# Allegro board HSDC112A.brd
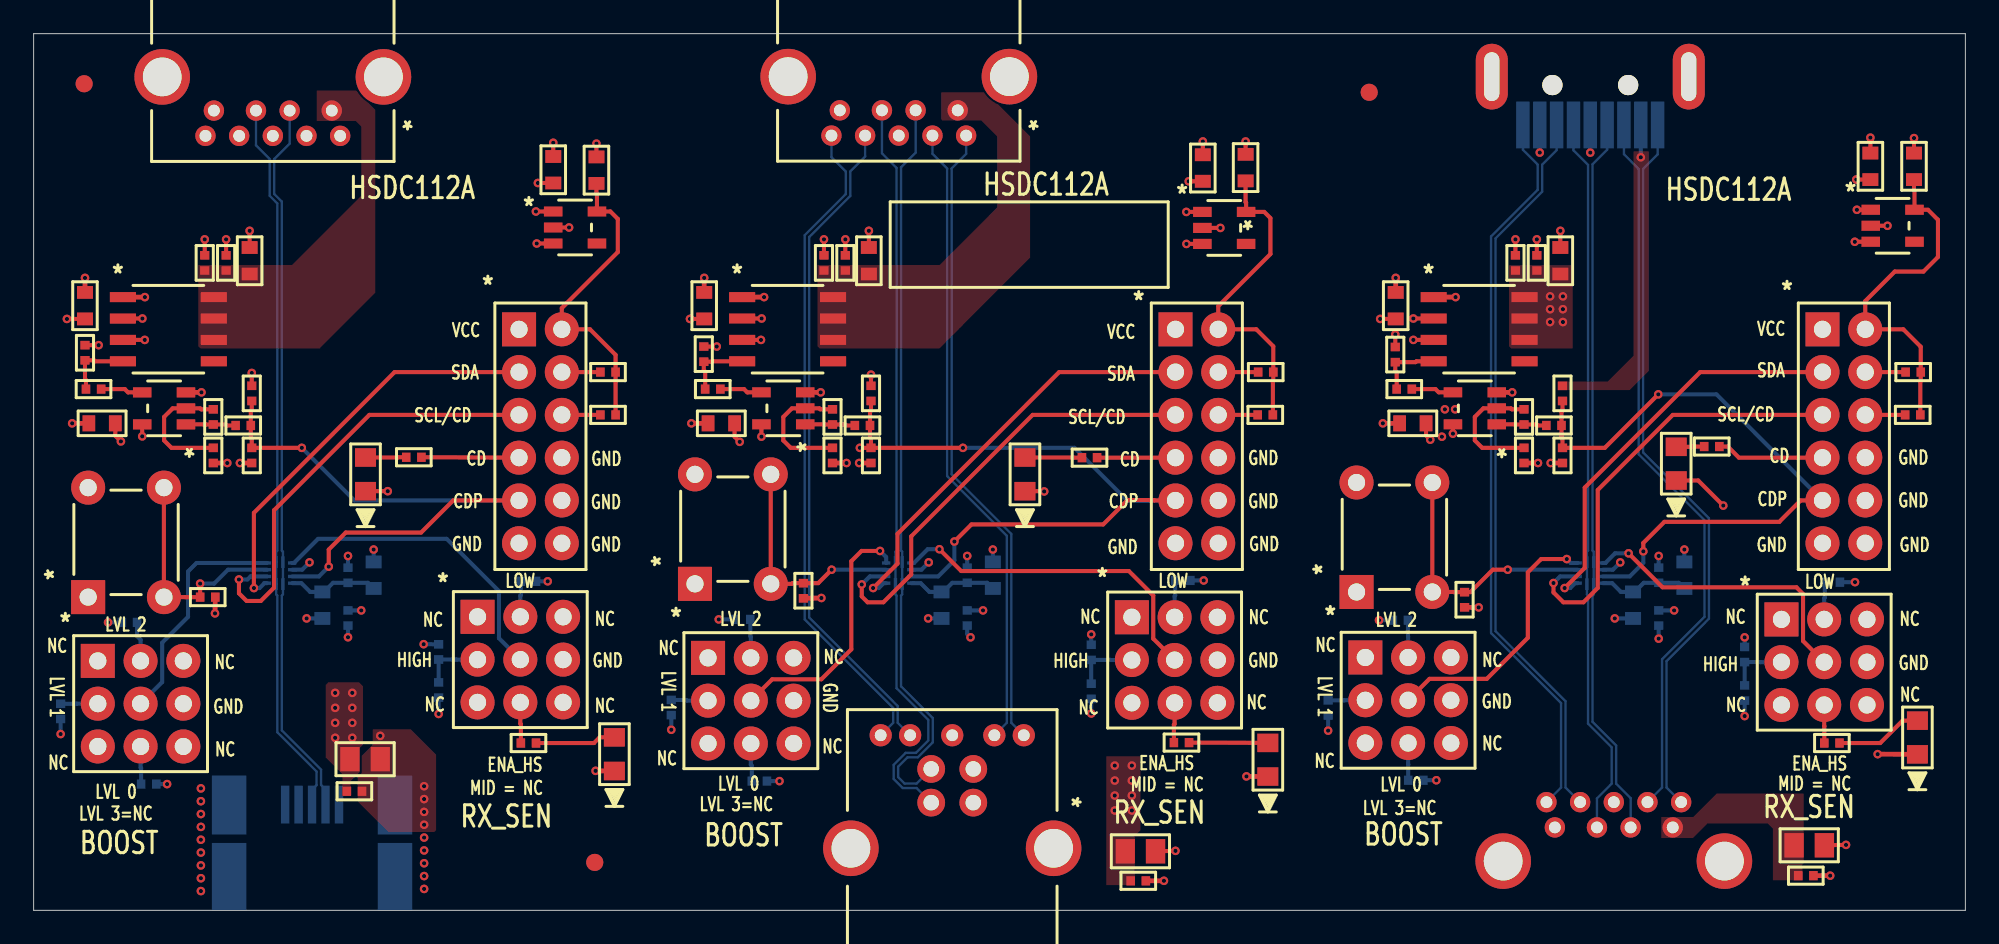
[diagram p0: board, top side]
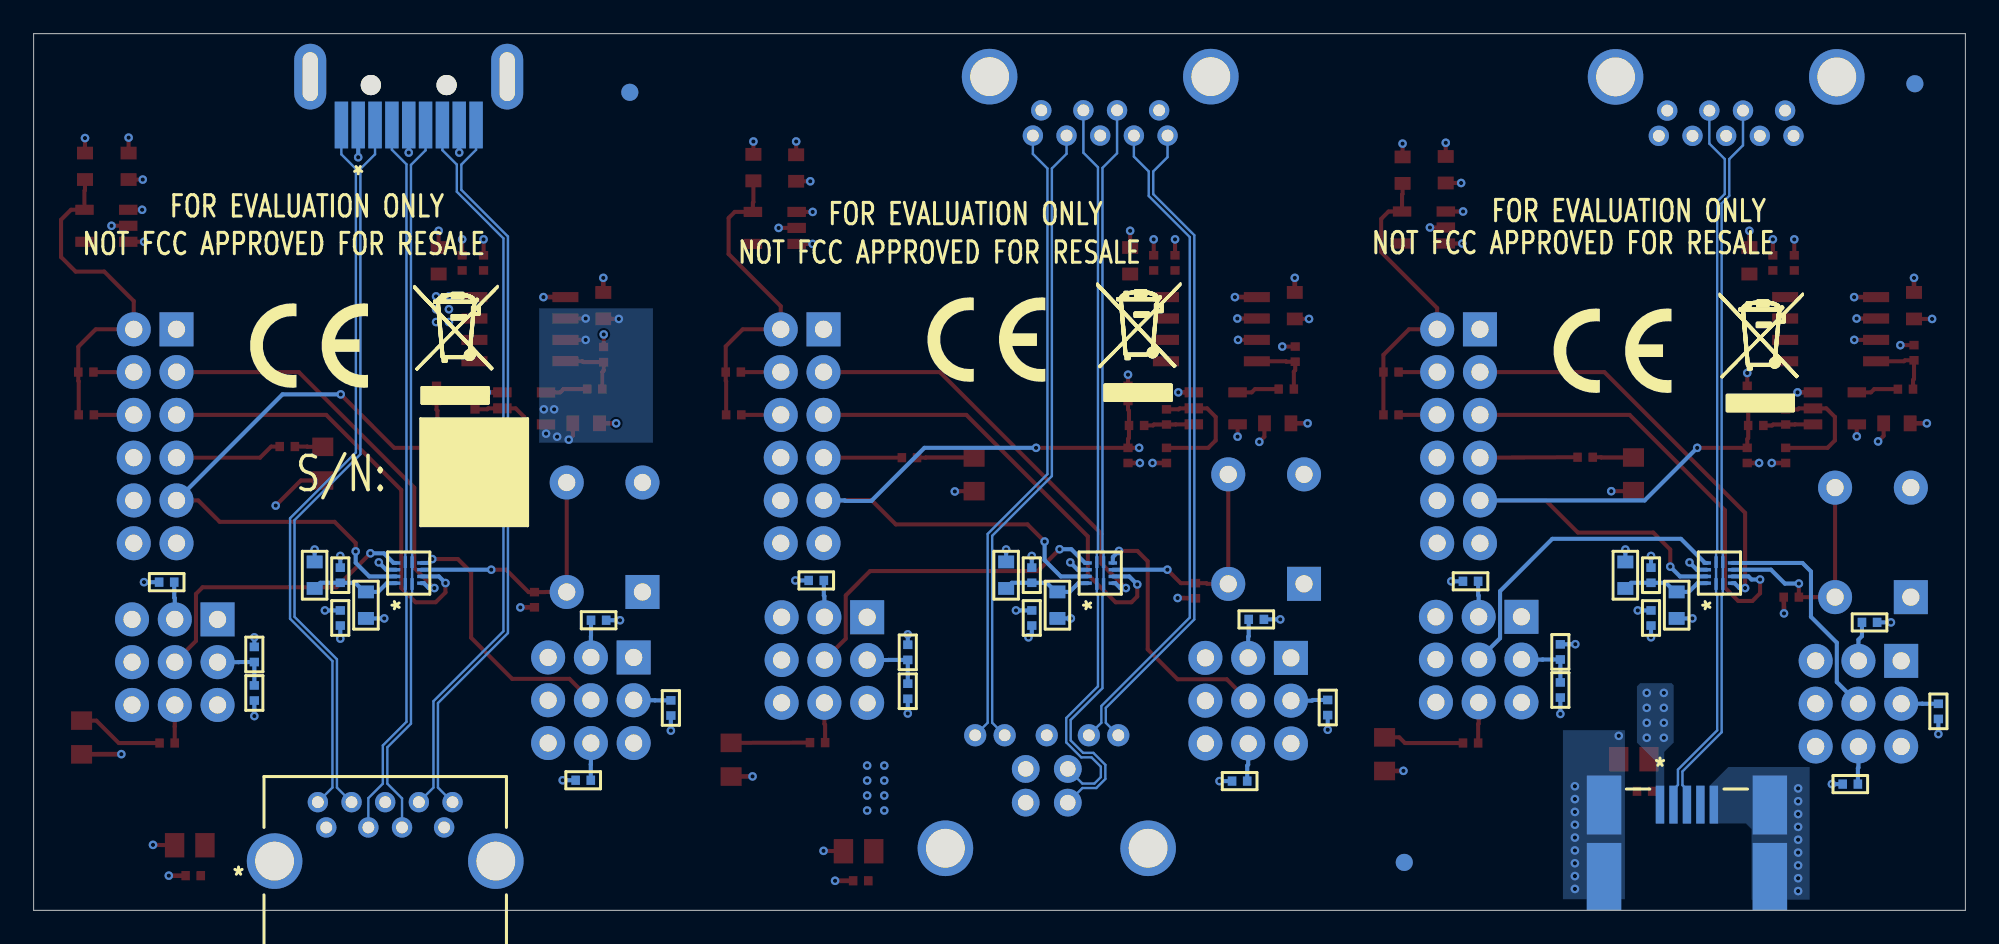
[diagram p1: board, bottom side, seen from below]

Outline 114.73 x 52.04 mm; copper layers: TOP, L2_PWR, L3_GND, BOTTOM. Coordinates in mm from the lower left corner of the outline.
Outline path: 0,52.04 114.73,52.04 114.73,0 0,0 0,52.04

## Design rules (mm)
constraint set DEFAULT: min track width 0.241
net group DIFFPAIR1: nets D1M_P1 D1P_P1
net group DIFFPAIR2: nets SS_RXN_P2 SS_RXP_P2
net group DIFFPAIR4: nets SS_TXN_P2 SS_TXP_P2
net group DIFFPAIR5: nets D1M_P2 D1P_P2
net group DIFFPAIR6: nets SS_TXN_P3 SS_TXP_P3
net group DIFFPAIR8: nets SS_RXN_P3 SS_RXP_P3
net group DIFFPAIR9: nets D1M_P3 D1P_P3

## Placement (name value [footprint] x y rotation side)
C1  0.1uF  [CAP_0402]  19.05 7.07 0 top
C2  10uF  [CAP_0805]  19.68 8.97 0 top
C3  1uF  [CAP_0603]  20.19 19.89 90 bottom
C4  0.1uF  [CAP_0402]  18.67 19.89 90 bottom
C5  0.1uF  [CAP_0402]  10.34 18.59 0 top
C6  1uF  [CAP_0603]  3.05 35.9 90 top
C7  2.2uF  [CAP_0603]  12.83 38.56 90 top
C8  0.1uF  [CAP_0402]  10.16 38.44 90 top
C9  0.1uF  [CAP_0402]  11.43 38.44 90 top
C10  1uF  [CAP_0603]  4.06 28.91 180 top
C11  4.7uF  [CAP_0402]  10.67 27.01 270 top
C12  0.1uF  [CAP_0402]  65.61 1.75 0 top
C13  10uF  [CAP_0805]  65.74 3.51 0 top
C14  1uF  [CAP_0603]  56.97 19.9 90 bottom
C15  0.1uF  [CAP_0402]  55.45 19.9 90 bottom
C16  0.1uF  [CAP_0402]  45.72 18.97 270 top
C17  2.2uF  [CAP_0603]  49.61 38.56 90 top
C18  0.1uF  [CAP_0402]  46.94 38.44 90 top
C19  0.1uF  [CAP_0402]  48.21 38.44 90 top
C20  1uF  [CAP_0603]  39.83 35.9 90 top
C21  1uF  [CAP_0603]  40.84 28.91 180 top
C22  4.7uF  [CAP_0402]  47.45 27.01 270 top
C23  0.1uF  [CAP_0402]  105.26 2.06 0 top
C24  10uF  [CAP_0805]  105.46 3.86 0 top
C25  1uF  [CAP_0603]  98.04 19.9 90 bottom
C26  0.1uF  [CAP_0402]  96.52 19.9 90 bottom
C27  0.1uF  [CAP_0402]  84.99 18.44 270 top
C28  2.2uF  [CAP_0603]  90.68 38.56 90 top
C29  0.1uF  [CAP_0402]  88.01 38.44 90 top
C30  0.1uF  [CAP_0402]  89.28 38.44 90 top
C31  1uF  [CAP_0603]  80.9 35.9 90 top
C32  1uF  [CAP_0603]  81.92 28.91 180 top
C33  4.7uF  [CAP_0402]  88.52 27.01 270 top
C34  1uF  [CAP_0603]  30.86 43.97 90 top
C35  2.2uF  [CAP_0603]  33.43 43.94 90 top
C36  1uF  [CAP_0603]  69.44 44.07 90 top
C37  2.2uF  [CAP_0603]  71.98 44.09 90 top
C38  1uF  [CAP_0603]  109.09 44.17 90 top
C39  2.2uF  [CAP_0603]  111.68 44.17 90 top
D1  LED  [LED_SM_LTST-C171]  19.71 25.88 90 top
D2  LED  [LED_SM_LTST-C171]  34.49 9.27 90 top
D3  LED  [LED_SM_LTST-C171]  73.3 8.94 90 top
D4  LED  [LED_SM_LTST-C171]  58.88 25.88 90 top
D5  LED  [LED_SM_LTST-C171]  111.89 10.26 90 top
D6  LED  [LED_SM_LTST-C171]  97.56 26.52 90 top
J1  HEADER 3x3  [HDR_THVT_3X3_254_871]  28.91 14.88 0 top
J2  HEADER 3x3  [HDR_THVT_3X3_254_871]  6.35 12.27 0 top
J3  HEADER 3x3  [HDR_THVT_3X3_254_871]  67.77 14.86 0 top
J4  HEADER 3x3  [HDR_THVT_3X3_254_871]  42.6 12.45 0 top
J5  HEADER 3x3  [HDR_THVT_3X3_254_871]  106.35 14.73 0 top
J6  HEADER 3x3  [HDR_THVT_3X3_254_871]  81.64 12.47 0 top
JMP1  Header 6x2  [HDR_THVT_2X6_254_871]  28.83 34.49 0 top
JMP8  Header 6x2  [HDR_THVT_2X6_254_871]  106.25 34.49 0 top
JMP9  Header 6x2  [HDR_THVT_2X6_254_871]  67.82 34.49 0 top
L1  100ohms  [FB_0603]  17.14 18.12 90 bottom
L2  100ohms  [FB_0603]  53.92 18.12 90 bottom
L3  100ohms  [FB_0603]  95 18.12 90 bottom
NOREF  -  []  23.24 43.26 0 top
NOREF#2  -  []  -3.81 -69.85 0 top
NOREF#3  -  []  0 52.04 0 top
NOREF#4  -  []  0 0 0 top
NOREF#5  -  []  114.73 0 90 top
NOREF#6  -  [unnamed#2]  33.32 2.84 0 top
NOREF#7  -  []  88.9 38.1 0 top
NOREF#8  -  []  60.6 43.38 0 top
NOREF#9  -  [unnamed#2]  3 49.07 0 top
NOREF#10  -  []  100.13 43.26 0 top
NOREF#11  -  [unnamed#2]  79.32 48.56 0 top
NOREF#12  -  [unnamed#2]  79.32 48.56 180 bottom
NOREF#13  -  []  20.95 33.22 180 bottom
NOREF#14  -  []  58.14 33.88 180 bottom
NOREF#15  -  []  98.73 26.01 180 bottom
NOREF#16  -  [unnamed#2]  33.32 2.84 180 bottom
NOREF#17  -  []  49.07 34.26 180 bottom
NOREF#18  -  []  98.37 33.53 180 bottom
NOREF#19  -  []  89.64 34.11 180 bottom
NOREF#20  -  []  12.12 33.66 180 bottom
NOREF#21  -  [unnamed#2]  3 49.07 180 bottom
P1  USB3.0 Type A Receptacle  [USB-A_THRT_GSB311131HR]  14.2 49.48 180 top
P2  Mini USB B  [USB-MB_SMRT_0548191572]  16.54 2 180 bottom
P3  USB3.0 Type A Receptacle  [USB-A_THRT_GSB311131HR]  51.38 49.49 180 top
P4  USB3.0 Type B Receptacle  [USB-B_THRT_GSB3211311WEU]  54.56 3.68 270 top
P5  USB3.0 Type A Receptacle  [USB-A_THRT_GSB311131HR]  93.85 2.92 180 bottom
P6  USB 3.0 Type A  [USB-A_SMRT_GSB316441CEU]  92.46 49.49 0 bottom
R1  0  [RES_0402]  18.67 17.35 90 bottom
R2  27 k  [RES_0402]  29.39 19.53 180 bottom
R3  1 k  [RES_0402]  3.05 33.1 270 top
R4  75  [RES_0402]  22.58 26.9 180 top
R5  75  [RES_0402]  29.39 9.93 0 top
R6  3.6 k  [RES_0402]  5.69 17.09 180 bottom
R7  0  [RES_0402]  6.83 7.49 0 bottom
R8  1.8 k  [RES_0402]  1.6 11.81 270 bottom
R9  13 k  [RES_0402]  24.05 15.34 270 bottom
R10  10k 1% DNI  [RES_0402]  12.95 30.69 270 top
R11  39 k  [RES_0402]  24.05 13.08 270 bottom
R12  0 DNI  [RES_0402]  3.56 30.94 0 top
R13  0 DNI  [RES_0402]  12.45 28.78 0 top
R14  22 k  [RES_0402]  10.67 29.29 270 top
R15  75k 1% DNI  [RES_0402]  12.95 27.01 270 top
R16  0  [RES_0402]  55.45 17.36 90 bottom
R17  1 k  [RES_0402]  39.8 33.02 90 top
R18  27 k  [RES_0402]  68.25 19.58 0 bottom
R19  75  [RES_0402]  62.71 26.87 180 top
R20  75  [RES_0402]  68.17 9.96 0 top
R21  3.6 k  [RES_0402]  42.11 17.27 180 bottom
R22  0  [RES_0402]  43.1 7.67 0 bottom
R23  10k 1% DNI  [RES_0402]  49.73 30.69 270 top
R24  1.8 k  [RES_0402]  37.87 12.04 270 bottom
R25  13 k  [RES_0402]  62.81 15.32 270 bottom
R26  0 DNI  [RES_0402]  40.34 30.94 0 top
R27  0 DNI  [RES_0402]  49.23 28.79 0 top
R28  22 k  [RES_0402]  47.45 29.29 270 top
R29  75k 1% DNI  [RES_0402]  49.73 27.01 270 top
R30  39 k  [RES_0402]  62.81 13 270 bottom
R31  0  [RES_0402]  96.52 17.36 90 bottom
R32  27 k  [RES_0402]  106.83 19.48 180 bottom
R33  1 k  [RES_0402]  80.87 32.99 90 top
R34  75  [RES_0402]  106.81 9.93 0 top
R35  75  [RES_0402]  99.67 27.53 180 top
R36  3.6 k  [RES_0402]  81.18 17.22 180 bottom
R37  0  [RES_0402]  82.09 7.72 0 bottom
R38  1.8 k  [RES_0402]  76.89 12.01 270 bottom
R39  13 k  [RES_0402]  101.63 15.19 270 bottom
R40  10k 1% DNI  [RES_0402]  90.81 30.69 270 top
R41  39 k  [RES_0402]  101.63 12.9 270 bottom
R42  0 DNI  [RES_0402]  81.41 30.94 0 top
R43  0 DNI  [RES_0402]  90.3 28.79 0 top
R44  22 k  [RES_0402]  88.52 29.29 270 top
R45  75k 1% DNI  [RES_0402]  90.81 27.01 270 top
R46  4.7 k  [RES_0402]  34.11 31.95 180 top
R47  4.7 k  [RES_0402]  34.11 29.41 180 top
R48  4.7 k  [RES_0402]  73.18 31.95 180 top
R49  4.7 k  [RES_0402]  73.15 29.41 180 top
R50  4.7 k  [RES_0402]  111.63 31.95 180 top
R51  4.7 k  [RES_0402]  111.61 29.41 180 top
SW1  Switch - Push Button  [SW_THVT_PTS645SL50-2]  5.49 21.84 90 top
SW2  Switch - Push Button  [SW_THVT_PTS645SL50-2]  41.53 22.63 90 top
SW3  Switch - Push Button  [SW_THVT_PTS645SL50-2]  80.82 22.15 90 top
U1  TUSB216I_217A_RWB  [RWB0012AA]  14.61 20.02 90 bottom
U2  TPS2024D  [D0008AA]  8 34.5 0 top
U3  SN74AHC1G86DBV  [DBV0005AB]  7.75 29.8 180 top
U4  TUSB216I_217A_RWB  [RWB0012AA]  51.38 20.02 90 bottom
U5  TPS2024D  [D0008AA]  44.78 34.5 0 top
U6  SN74AHC1G86DBV  [DBV0005AB]  44.53 29.8 180 top
U7  TUSB216I_217A_RWB  [RWB0012AA]  92.46 20.02 90 bottom
U8  TPS2024D  [D0008AA]  85.85 34.5 0 top
U9  SN74AHC1G86DBV  [DBV0005AB]  85.6 29.8 180 top
U10  TPS70633  [DBV0005AB]  32.16 40.54 0 top
U11  TPS70633  [DBV0005AB]  70.71 40.51 0 top
U12  TPS70633  [DBV0005AB]  110.41 40.64 0 top

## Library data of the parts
C1 C4 C5 C8 C9 C11 C12 C15 C16 C18 C19 C22 C23 C26 C27 C29 C30 C33 = cc0402
C2 C13 C24 = CAPACITOR POL
C3 C6 C7 C10 C14 C17 C20 C21 C25 C28 C31 C32 C34-C39 = cc0603
D1 D4 D6 = d0805 Blue
D2 D3 D5 = d0805 Green
J1-J6 = HEADER 3x3_0
JMP1 JMP8 JMP9 = Header 6x2
L1-L3 = Ferrite_Bead_500ohm
P1 P3 P5 = USB 3.0 Type A Receptacle
P2 = Mini USB B_3
P4 = USB 3.0 Type B Receptacle
P6 = USB 3_1.0 Type A
R1-R51 = r0402
SW1-SW3 = Switch - Push Button_0
U1 U4 U7 = TUSB216RWB_2
U2 U5 U8 = TPS2024_D_1
U3 U6 U9 = SN74AHC1G86_DBV_
U10-U12 = TPS706

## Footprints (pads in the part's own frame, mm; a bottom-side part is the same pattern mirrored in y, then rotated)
CAP_0402
  rect 0.51x0.55 smd: 1(-0.45,0) 2(0.45,0)
CAP_0603
  rect 0.76x0.95 smd: 1(-0.787,0) 2(0.787,0)
CAP_0805
  rect 1.15x1.45 smd: 1(-0.9,0) 2(0.9,0)
D0008AA
  rect 1.55x0.6 smd: 1(-2.7,1.905) 2(-2.7,0.635) 3(-2.7,-0.635) 4(-2.7,-1.905) 5(2.7,-1.905) 6(2.7,-0.635) 7(2.7,0.635) 8(2.7,1.905)
DBV0005AB
  rect 1.1x0.6 smd: 1(-1.3,0.95) 2(-1.3,0) 3(-1.3,-0.95) 4(1.3,-0.95) 5(1.3,0.95)
FB_0603
  rect 0.76x0.95 smd: 1(-0.787,0) 2(0.787,0)
HDR_THVT_2X6_254_871
  rect 2.02x2.02 hole 1.02: 1(0,0)
  round 2.02 hole 1.02: 2(2.54,0) 3(0,-2.54) 4(2.54,-2.54) 5(0,-5.08) 6(2.54,-5.08) 7(0,-7.62) 8(2.54,-7.62) 9(0,-10.16) 10(2.54,-10.16) 11(0,-12.7) 12(2.54,-12.7)
HDR_THVT_3X3_254_871
  rect 2.02x2.02 hole 1.02: 1(-2.54,2.54)
  round 2.02 hole 1.02: 2(0,2.54) 3(2.54,2.54) 4(-2.54,0) 5(0,0) 6(2.54,0) 7(-2.54,-2.54) 8(0,-2.54) 9(2.54,-2.54)
LED_SM_LTST-C171
  rect 1.1x1.25 smd: 1(-1,0) 2(1,0)
RES_0402
  rect 0.51x0.55 smd: 1(-0.45,0) 2(0.45,0)
RWB0012AA
  rect 0.7x0.2 smd: 1(-0.65,0.2) 2(-0.65,-0.2) 7(0.65,-0.2) 8(0.65,0.2)
  rect 0.2x0.5 smd: 3(-0.6,-0.75) 4(-0.2,-0.75) 5(0.2,-0.75) 6(0.6,-0.75) 9(0.6,0.75) 10(0.2,0.75) 11(-0.2,0.75) 12(-0.6,0.75)
SW_THVT_PTS645SL50-2
  rect 2.02x2.02 hole 1.02: 1(-3.25,2.25)
  round 2.02 hole 1.02: 2(3.25,2.25) 3(-3.25,-2.25) 4(3.25,-2.25)
unnamed#2
  round 1.016 smd: (0,0)
USB-A_SMRT_GSB316441CEU
  round 1.2 hole 1.2 unplated: (-2.25,0.5) (2.25,0.5)
  rect 0.8x2.78 smd: 1(3,2.87) 2(1,2.87) 3(-1,2.87) 4(-3,2.87) 5(-4,2.87) 6(-2,2.87) 7(0,2.87) 8(2,2.87) 9(4,2.87)
  oval 1.9x3.9 hole 0.9x2.9: 10(-5.85,0) 11(5.85,0)
USB-A_THRT_GSB311131HR
  round 1.21 hole 0.7: 1(-3.5,2) 2(-1,2) 3(1,2) 4(3.5,2) 5(4,3.5) 6(2,3.5) 7(0,3.5) 8(-2,3.5) 9(-4,3.5)
  round 3.3 hole 2.3: 10(-6.57,0) 11(6.57,0)
USB-B_THRT_GSB3211311WEU
  round 1.65 hole 0.92: 1(-4.71,1.25) 2(-4.71,-1.25) 3(-2.71,-1.25) 4(-2.71,1.25)
  round 1.32 hole 0.7: 5(-6.71,-4.25) 6(-6.71,-2.5) 7(-6.71,0) 8(-6.71,2.5) 9(-6.71,4.25)
  round 3.3 hole 2.3: 10(0,6.02) 11(0,-6.02)
USB-MB_SMRT_0548191572
  rect 0.5x2.25 smd: 1(-1.6,4.275) 2(-0.8,4.275) 3(0,4.275) 4(0.8,4.275) 5(1.6,4.275)
  rect 2.05x3.5 smd: 6(4.925,4.25) 9(-4.925,4.25)
  rect 2.05x4 smd: 7(4.925,0) 8(-4.925,0)

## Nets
GND: C1.2 C2.2 C3.2 C4.2 C5.2 C6.2 C7.2 C8.2 C9.2 C10.2 C11.2 C12.2 C13.2 C14.2 C15.2 C16.2 C17.2 C18.2 C19.2 C20.2 C21.2 C22.2 C23.2 C24.2 C25.2 C26.2 C27.2 C28.2 C29.2 C30.2 C31.2 C32.2 C33.2 C34.2 C35.2 C36.2 C37.2 C38.2 C39.2 D1.1 D2.1 D3.1 D4.1 D5.1 D6.1 J1.6 J2.6 J3.6 J4.6 J5.6 J6.6 JMP1.8 JMP1.10 JMP1.11 JMP1.12 JMP8.8 JMP8.10 JMP8.11 JMP8.12 JMP9.8 JMP9.10 JMP9.11 JMP9.12 P1.4 P1.7 P1.10 P1.11 P2.5 P2.6 P2.7 P2.8 P2.9 P3.4 P3.7 P3.10 P3.11 P4.4 P4.7 P4.10 P4.11 P5.4 P5.7 P5.10 P5.11 P6.4 P6.7 P6.10 P6.11 R2.1 R3.1 R6.2 R7.2 R8.2 R11.2 R15.2 R17.2 R18.2 R21.2 R22.2 R24.2 R29.2 R30.2 R32.1 R33.2 R36.2 R37.2 R38.2 R41.2 R45.2 SW1.1 SW1.2 SW2.1 SW2.2 SW3.1 SW3.2 U1.10 U2.1 U3.3 U4.10 U5.1 U6.3 U7.10 U8.1 U9.3 U10.2 U11.2 U12.2
VBUS_DS_P1: C7.1 C8.1 C9.1 P1.1(VBUS) U2.6 U2.7 U2.8(OUT_2)
VBUS_DS_P2: C17.1 C18.1 C19.1 P3.1(VBUS) U5.6 U5.7 U5.8(OUT_2)
VBUS_DS_P3: C23.1 C24.1 C28.1 C29.1 C30.1 P5.1(VBUS) U8.6 U8.7 U8.8(OUT_2)
VBUS_US_P3: P6.1(VBUS) R31.1 R40.1
VCC_EXT_P1: C6.1 C10.1 C34.1 JMP1.1 L1.1 R1.2 R9.1 U2.2 U2.3 U3.5 U10.1 U10.3
VCC_EXT_P2: C20.1 C21.1 C36.1 JMP9.1 L2.1 R16.2 R25.1 U5.2 U5.3 U6.5 U11.1 U11.3
VCC_EXT_P3: C31.1 C32.1 C38.1 JMP8.1 L3.1 R31.2 R39.1 U8.2 U8.3 U9.5 U12.1 U12.3
VCC_US_P1: C1.1 C2.1 P2.1(VBUS) R1.1 R10.1
VCC_US_P2: C12.1 C13.1 P4.1(VBUS) R16.1 R23.1
BOOST_P1: J2.5 U1.6
BOOST_P2: J4.5 U4.6
BOOST_P3: J6.5 U7.6
CD_P1: JMP1.7 R4.1
CD_P2: JMP9.7 R19.1
CD_P3: JMP8.7 R35.1
CDP_ENZ_P1: JMP1.9 R10.2 R13.2 R15.1 U1.11
CDP_ENZ_P2: JMP9.9 R23.2 R27.2 R29.1 U4.11
CDP_ENZ_P3: JMP8.9 R40.2 R43.2 R45.1 U7.11
D1M_P1: P1.2 P2.2 U1.1 U1.8
D1M_P2: P3.2 P4.2 U4.1 U4.8
D1M_P3: P5.2 P6.2 U7.1 U7.8
D1P_P1: P1.3 P2.3 U1.2 U1.7
D1P_P2: P3.3 P4.3 U4.2 U4.7
D1P_P3: P5.3 P6.3 U7.2 U7.7
DCP_CDP_TOGGLE_P1: R3.2 R12.1 U2.4
DCP_CDP_TOGGLE_P2: R17.1 R26.1 U5.4
DCP_CDP_TOGGLE_P3: R33.1 R42.1 U8.4
ENA_HS_P1: J1.8 R5.1
ENA_HS_P2: J3.8 R20.1
ENA_HS_P3: J5.8 R34.1
RSTN_P1: C5.1 SW1.3 SW1.4 U1.5
RSTN_P2: C16.1 SW2.3 SW2.4 U4.5
RSTN_P3: C27.1 SW3.3 SW3.4 U7.5
RX_SEN/ENA_HS_P1: J1.5 U1.9
RX_SEN/ENA_HS_P2: J3.5 U4.9
RX_SEN/ENA_HS_P3: J5.5 U7.9
SCL/CD_P1: JMP1.5 U1.4
SCL/CD_P2: JMP9.5 U4.4
SCL/CD_P3: JMP8.5 U7.4
SDA_P1: JMP1.3 U1.3
SDA_P2: JMP9.3 U4.3
SDA_P3: JMP8.3 U7.3
SS_RXN_P2: P3.5 P4.5
SS_RXN_P3: P5.5 P6.5
SS_RXP_P2: P3.6 P4.6
SS_RXP_P3: P5.6 P6.6
SS_TXN_P2: P3.8 P4.8
SS_TXN_P3: P5.8 P6.8
SS_TXP_P2: P3.9 P4.9
SS_TXP_P3: P5.9 P6.9
SW_VCC_P1: C35.1 JMP1.2 R46.1 R47.1 U10.5(VOUT)
SW_VCC_P2: C37.1 JMP9.2 R48.1 R49.1 U11.5(VOUT)
SW_VCC_P3: C39.1 JMP8.2 R50.1 R51.1 U12.5(VOUT)
N16790170: R27.1 R28.2 U6.1
N16790175: C22.1 R28.1 U6.2
N16793543: R26.2 U6.4(Y)
N16795852: R43.1 R44.2 U9.1
N16795856: C33.1 R44.1 U9.2
N16796357: R42.2 U9.4(Y)
N16796414: D6.2 R35.2
N16797569: R13.1 R14.2 U3.1
N16798025: C3.1 C4.1 L1.2 U1.12(VCC)
N16798074: R12.2 U3.4(Y)
N16798131: D1.2 R4.2
N16810380: J1.4 R9.2 R11.1
N16810407: J2.8 R7.1
N16810514: J2.2 R6.1
N16813878: C14.1 C15.1 L2.2 U4.12(VCC)
N16814597: C25.1 C26.1 L3.2 U7.12(VCC)
N16860679: J3.4 R25.2 R30.1
N16860703: J4.8 R22.1
N16860789: J4.2 R21.1
N16861643: J5.4 R39.2 R41.1
N16861663: J6.4 R38.1
N16861667: J6.8 R37.1
N16861753: J6.2 R36.1
N16876268: C11.1 R14.1 U3.2
N16883773: D4.2 R19.2
N16915178: JMP1.4 R46.2
N16915181: JMP1.6 R47.2
N16916526: JMP9.6 R49.2
N16916965: JMP9.4 R48.2
N16917043: JMP8.6 R51.2
N16917272: JMP8.4 R50.2
N16929690: J1.2 R2.2
N16931613: J2.4 R8.1
N16933252: J3.2 R18.1
N16935144: J4.4 R24.1
N16936334: J5.2 R32.2
N168104220: D2.2 R5.2
N168607180: D3.2 R20.2
N168616820: D5.2 R34.2

Pads without a net: J1 1 3 7 9; J2 1 3 7 9; J3 1 3 7 9; J4 1 3 7 9; J5 1 3 7 9; J6 1 3 7 9; P1 5 6 8 9; P2 4; U2 5; U5 5; U8 5; U10 4; U11 4; U12 4

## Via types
v1: diameter 0.508, hole 0.254, TOP to BOTTOM, 181 vias

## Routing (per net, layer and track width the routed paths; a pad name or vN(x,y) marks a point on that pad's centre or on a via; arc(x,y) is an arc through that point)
GND: length 277.6
  TOP w0.241: C37.2 v1(71.98,45.64) ; U3.3 9.1,30.75 ; U6.3 45.88,30.75 ; v1(100.36,24.03) 98.87,25.52 D6.1 ; C18.2 v1(46.94,39.83) ; C19.2 v1(48.21,39.83) ; C38.2 v1(109.09,45.87) ; C39.2 v1(111.68,45.85) ; R33.2 v1(80.87,34.19) ; C30.2 v1(89.28,39.83) ; C35.2 v1(33.43,45.52) ; C28.2 v1(90.68,40.34) ; R17.2 v1(40.57,33.47) ; R3.1 v1(3.86,33.55) ; C8.2 v1(10.16,39.83) ; C29.2 v1(88.01,39.83) ; C36.2 v1(69.44,45.64) ; U10.2 v1(31.8,40.54) ; C17.2 v1(49.61,40.34) ; D1.1 v1(21.03,24.88) ; C13.2 v1(67.82,3.53) ; C34.2 v1(30.86,45.57) ; C9.2 v1(11.43,39.83) ; D4.1 59.75,24.88 59.77,24.87 v1(60.02,24.87) ; C24.2 v1(107.65,3.89) ; C7.2 v1(12.83,40.34) ; U11.2 v1(70.48,40.51) ; U12.2 v1(110.11,40.64) ; U9.3 86.95,30.75
  TOP w0.279: R29.2 v1(49.03,26.56) ; C12.2 v1(67.13,1.75) ; U5.1 v1(43.38,36.41) ; C31.2 v1(80.9,37.55) ; D2.1 v1(33.38,8.28) ; C16.2 v1(46.79,18.54) ; C20.2 v1(39.83,37.55) ; U2.1 v1(6.6,36.4) ; D5.1 v1(109.52,9.27) ; C33.2 v1(89.35,26.56) ; U8.1 v1(84.45,36.41) ; C21.2 v1(39.07,28.91) ; C27.2 v1(85.83,17.98) ; R15.2 v1(12.25,26.56) ; C6.2 v1(3.05,37.55) ; C32.2 v1(80.14,28.91) ; C23.2 v1(106.71,2.06) ; 9.1,30.75 v1(9.97,30.75) ; C11.2 v1(11.5,26.56) ; 45.88,30.75 v1(46.75,30.75) ; R45.2 v1(90.1,26.56) ; C10.2 v1(2.29,28.91) ; C5.2 v1(10.77,17.63) ; C22.2 v1(48.28,26.56) ; D3.1 v1(72.03,7.95) ; 86.95,30.75 v1(87.82,30.75)
  L3_GND w0.241: JMP1.12 32.56,21.79 ; JMP1.12 30.18,21.79 ; JMP1.12 31.37,22.98 ; JMP1.12 31.37,20.6 ; 51.38,45.21 P3.7 ; P3.7 51.38,46.78 ; P3.7 52.17,45.99 ; P3.7 50.6,45.99 ; 31.37,25.68 JMP1.8 ; JMP1.8 32.56,26.87 ; JMP1.8 30.18,26.87 ; JMP1.8 31.37,28.06 ; J6.6 84.18,13.66 ; J6.6 82.99,12.47 ; J6.6 84.18,11.28 ; J6.6 85.36,12.47 ; 7.7,12.27 J2.6 ; J2.6 10.08,12.27 ; J2.6 8.89,13.46 ; J2.6 8.89,11.08 ; P6.11 99.43,49.49 ; P6.11 97.18,49.49 ; P6.11 98.31,47.37 ; JMP8.11 107.44,21.79 ; JMP8.11 106.25,20.6 ; JMP8.11 105.06,21.79 ; JMP8.11 106.25,22.98 ; 57.95,47.67 P3.10 ; P3.10 56.13,49.49 ; P3.10 59.78,49.49 ; J1.6 31.45,16.07 ; J1.6 31.45,13.7 ; J1.6 30.26,14.88 ; J1.6 32.63,14.88 ; 70.36,20.6 JMP9.12 ; JMP9.12 70.36,22.98 ; JMP9.12 69.17,21.79 ; JMP9.12 71.55,21.79 ; 108.79,20.6 JMP8.12 ; JMP8.12 107.6,21.79 ; JMP8.12 109.98,21.79 ; JMP8.12 108.79,22.98 ; 31.37,23.14 JMP1.10 ; JMP1.10 32.56,24.33 ; JMP1.10 30.18,24.33 ; JMP1.10 31.37,25.52 ; 87.28,2.92 89.11,2.92 ; 87.28,2.92 87.28,4.75 ; 87.28,2.92 85.45,2.92 ; 87.28,2.92 87.28,1.09 ; 7.63,47.65 P1.11 ; P1.11 9.46,49.48 ; P1.11 5.81,49.48 ; JMP1.11 28.83,22.98 ; JMP1.11 28.83,20.6 ; JMP1.11 30.02,21.79 ; JMP1.11 27.64,21.79 ; 93.07,6.42 P5.7 ; P5.7 93.85,7.2 ; P5.7 93.85,5.64 ; P5.7 94.64,6.42 ; SW2.1 40.47,19.38 ; SW2.1 39.28,20.57 ; SW2.1 39.28,18.19 ; SW2.1 38.09,19.38 ; P5.10 102.25,2.92 ; P5.10 100.42,4.75 ; P5.10 98.59,2.92 ; P5.10 100.42,1.09 ; 77.38,18.9 SW3.1 ; SW3.1 78.57,20.09 ; SW3.1 78.57,17.71 ; SW3.1 79.76,18.9 ; 3.24,17.41 SW1.1 ; SW1.1 2.05,18.59 ; SW1.1 4.42,18.59 ; SW1.1 3.24,19.78 ; SW3.2 79.76,25.4 ; SW3.2 78.57,24.21 ; SW3.2 77.38,25.4 ; SW3.2 78.57,26.59 ; 2.05,25.09 SW1.2 ; SW1.2 3.24,26.28 ; SW1.2 3.24,23.91 ; SW1.2 4.42,25.09 ; P4.4 56.81,6.39 ; P4.4 55.81,5.39 ; P4.4 54.81,6.39 ; 43.95,12.45 J4.6 ; J4.6 45.14,11.26 ; J4.6 45.14,13.63 ; J4.6 46.32,12.45 ; 70.36,23.14 JMP9.10 ; JMP9.10 71.55,24.33 ; JMP9.10 69.17,24.33 ; JMP9.10 70.36,25.52 ; JMP9.11 69.01,21.79 ; JMP9.11 66.63,21.79 ; JMP9.11 67.82,20.6 ; JMP9.11 67.82,22.98 ; 13.42,45.98 P1.7 ; P1.7 14.99,45.98 ; P1.7 14.2,46.76 ; P1.7 14.2,45.2 ; P1.10 22.6,49.48 ; P1.10 18.95,49.48 ; P1.10 20.77,47.65 ; 39.28,24.69 SW2.2 ; SW2.2 39.28,27.07 ; SW2.2 40.47,25.88 ; SW2.2 38.09,25.88 ; 85.48,49.49 P6.10 ; P6.10 86.61,47.37 ; P6.10 87.73,49.49 ; JMP8.10 108.79,25.52 ; JMP8.10 107.6,24.33 ; JMP8.10 109.98,24.33 ; JMP8.10 108.79,23.14 ; 90.35,4.14 P5.4 ; P5.4 89.57,4.92 ; P5.4 91.14,4.92 ; 35.51,51.23 36.98,51.23 ; P1.4 11.49,47.48 ; P1.4 10.7,48.26 ; P1.4 9.92,47.48 ; 60.58,1.85 P4.10 ; P4.10 60.58,5.51 ; P4.10 58.75,3.68 ; P4.10 62.41,3.68 ; 48.54,3.68 50.37,3.68 ; 48.54,3.68 46.71,3.68 ; 48.54,3.68 48.54,1.85 ; 48.54,3.68 48.54,5.51 ; JMP8.8 108.79,28.06 ; JMP8.8 107.6,26.87 ; JMP8.8 108.79,25.68 ; JMP8.8 109.98,26.87 ; J5.6 110.08,14.73 ; J5.6 108.89,13.54 ; J5.6 108.89,15.92 ; J5.6 107.7,14.73 ; 69.17,26.87 JMP9.8 ; JMP9.8 70.36,25.68 ; JMP9.8 70.36,28.06 ; JMP9.8 71.55,26.87 ; 70.31,13.67 J3.6 ; J3.6 69.12,14.86 ; J3.6 71.5,14.86 ; J3.6 70.31,16.05 ; P4.7 54.56,11.23 ; P4.7 54.56,9.55 ; P4.7 55.4,10.39 ; P4.7 53.72,10.39 ; 42.99,49.49 P3.11 ; P3.11 46.64,49.49 ; P3.11 44.81,47.67 ; 47.1,47.49 P3.4 ; P3.4 48.67,47.49 ; P3.4 47.88,48.28 ; 74.37,51.13 76.07,51.13
  BOTTOM w0.241: R32.1 v1(108.18,19.48) ; U4.10 52.73,20.22 v1(53.16,20.66) ; C26.2 v1(96.52,21.04) ; R30.2 v1(62.81,11.68) ; C25.2 v1(98.04,21.42) ; U1.10 15.95,20.22 v1(16.38,20.66) ; R24.2 v1(37.87,10.72) ; R11.2 v1(24.05,11.66) ; U7.10 93.8,20.22 v1(94.23,20.66) ; P6.7 v1(92.46,44.98) ; R7.2 v1(7.92,7.49) ; R22.2 v1(44.3,7.67) ; C15.2 v1(55.45,21.04) ; R6.2 v1(4.42,17.09) ; C14.2 v1(56.97,21.42) ; R8.2 v1(1.6,10.46) ; R2.1 v1(30.53,19.53) ; R37.2 v1(83.31,7.72) ; R36.2 v1(79.91,17.22) ; R21.2 v1(40.69,17.27) ; R38.2 v1(76.89,10.67) ; C4.2 v1(18.67,21.04) ; R18.2 v1(69.49,19.58) ; P6.4 v1(89.46,44.99) ; C3.2 v1(20.19,21.42) ; R41.2 v1(101.63,11.53)
  vias: v1(9.93,7.24) v1(9.93,6.48) v1(9.93,5.71) v1(9.93,4.95) v1(9.93,4.19) v1(9.93,3.43) v1(9.93,2.67) v1(9.93,1.91) v1(9.93,1.14) v1(20.58,10.36) v1(23.19,7.37) v1(23.19,6.6) v1(23.19,5.84) v1(23.19,5.08) v1(23.19,4.32) v1(23.19,3.56) v1(23.19,2.79) v1(23.19,2.03) v1(23.19,1.27)
VBUS_DS_P3:
  vias: v1(90.07,36.45) v1(90.07,35.69) v1(90.07,34.92) v1(90.83,36.45) v1(90.83,35.69) v1(90.83,34.92)
VBUS_US_P3: length 2.7
  BOTTOM w0.241: P6.1 v1(95.46,44.71) ; R31.1 v1(96.52,16.13)
VCC_EXT_P1: length 15.7
  TOP w0.241: C34.1 v1(29.95,43.18) ; U3.5 v1(6.45,28.14) ; C6.1 v1(1.97,35.11) ; U2.2 v1(6.46,35.13) ; v1(5.18,27.84) 4.85,28.17 C10.1 ; U2.3 v1(6.6,33.86) ; U10.1 v1(29.83,41.49) ; U10.3 v1(29.88,39.59)
  L2_PWR w0.241: 27.64,34.49 JMP1.1 ; JMP1.1 28.83,33.3 ; JMP1.1 30.02,34.49 ; JMP1.1 28.83,35.68
  BOTTOM w0.241: R1.2 v1(19.46,17.8) ; L1.1 v1(16.21,17.33) ; R9.1 v1(23.16,15.8)
VCC_EXT_P2: length 14.9
  TOP w0.241: C20.1 v1(38.98,35.11) ; C21.1 41.63,28.12 v1(41.94,27.81) ; U11.1 v1(68.46,41.46) ; U5.3 v1(43.2,33.87) ; U6.5 v1(43.23,28.12) ; U5.2 v1(43.24,35.14) ; U11.3 v1(68.47,39.56) ; C36.1 v1(68.61,43.28)
  L2_PWR w0.241: JMP9.1 67.82,35.68 ; JMP9.1 69.01,34.49 ; JMP9.1 66.63,34.49 ; JMP9.1 67.82,33.3
  BOTTOM w0.241: L2.1 v1(53.13,17.33) ; R25.1 v1(62.81,16.38) ; R16.2 v1(56.39,17.81)
VCC_EXT_P3: length 14.9
  TOP w0.241: U8.3 v1(81.95,33.87) ; U8.2 v1(81.95,35.14) ; v1(82.95,27.94) 82.7,28.19 C32.1 ; U12.3 v1(108.17,39.69) ; U9.5 v1(84.3,28.3) ; C38.1 v1(108.25,43.38) ; U12.1 v1(108.29,41.59) ; C31.1 v1(79.98,35.11)
  L2_PWR w0.241: JMP8.1 106.25,35.68 ; JMP8.1 105.06,34.49 ; JMP8.1 106.25,33.3 ; JMP8.1 107.44,34.49
  BOTTOM w0.241: L3.1 v1(93.91,17.33) ; R31.2 v1(97.43,17.81) ; R39.1 v1(101.63,16.21)
  vias: v1(83.64,28.12) v1(83.82,29.74) v1(84.43,29.74)
VCC_US_P1: length 1.5
  TOP w0.241: R10.1 v1(12.95,31.9)
  BOTTOM w0.241: R1.1 v1(18.67,16.21)
  vias: v1(17.91,12.91) v1(17.91,12.02) v1(17.91,11.13) v1(17.91,10.24) v1(18.92,12.91) v1(18.92,12.02) v1(18.92,11.13) v1(18.92,10.24)
VCC_US_P2: length 4.5
  TOP w0.241: R23.1 v1(49.73,31.8)
  L2_PWR w0.241: P4.1 56.81,8.39 ; P4.1 55.81,9.4 ; P4.1 54.81,8.39
  BOTTOM w0.241: v1(55.65,16.21) 55.45,16.4 R16.1
  vias: v1(64.21,8.59) v1(64.21,7.7) v1(64.21,6.81) v1(64.21,5.93) v1(65.23,8.59) v1(65.23,7.7) v1(65.23,6.81) v1(65.23,5.93)
BOOST_P1: length 13.9
  BOTTOM w0.241: J2.5 7.63,13.55 7.63,15.89 9.17,17.42 9.17,20.12 9.67,20.62 U1.6
BOOST_P2: length 15.3
  TOP w0.241: J4.5 43.87,13.72 46.79,13.72 48.56,15.49 48.56,20.73 49.17,21.34 v1(50.27,21.34)
  BOTTOM w0.241: v1(50.27,21.34) 50.63,20.97 U4.6
BOOST_P3: length 15.9
  TOP w0.241: v1(91.06,20.85) 89.53,20.85 88.75,20.07 88.75,16.18 86.31,13.74 82.91,13.74 J6.5
  BOTTOM w0.241: v1(91.06,20.85) 91.29,20.62 U7.6
CD_P1: length 5.8
  TOP w0.241: JMP1.7 R4.1
CD_P2: length 4.7
  TOP w0.241: R19.1 JMP9.7
CD_P3: length 6.4
  TOP w0.241: R35.1 100.62,27.53 101.28,26.87 JMP8.7
CDP_ENZ_P1: length 35.9
  TOP w0.241: v1(15.93,27.46) R15.1 12.95,27.98 12.9,28.04 R13.2 12.9,29.66 12.95,29.72 R10.2 ; v1(17.53,20.4) 17.53,21.42 18.54,22.43 23.01,22.43 24.92,24.33 JMP1.9
  BOTTOM w0.241: v1(17.53,20.4) 16.95,19.82 U1.11 ; JMP1.9 19.05,24.33 v1(15.93,27.46)
CDP_ENZ_P2: length 41.1
  TOP w0.241: R23.2 49.73,29.72 49.68,29.66 R27.2 49.68,28.04 49.73,27.98 R29.1 ; R29.1 v1(49.07,27.46) ; R29.1 v1(55.19,27.46) ; JMP9.9 66.56,24.33 66.53,24.36 64.97,24.36 63.53,22.91 55.7,22.91 v1(54.69,21.89)
  BOTTOM w0.241: v1(55.19,27.46) 61.82,27.46 64.97,24.31 66.53,24.31 66.56,24.33 JMP9.9 ; v1(54.69,21.89) 54.69,20.78 53.72,19.82 U4.11
CDP_ENZ_P3: length 37.8
  TOP w0.241: JMP8.9 104.95,24.33 103.68,23.06 96.86,23.06 95.61,21.81 v1(95.61,21.31) ; R40.2 90.81,29.72 90.75,29.66 R43.2 90.75,28.04 90.81,27.98 R45.1 93.32,27.46 v1(96.49,30.63)
  BOTTOM w0.241: v1(96.49,30.63) 99.95,30.63 JMP8.9 ; v1(95.61,21.31) 95.61,20.63 94.8,19.82 U7.11
D1M_P1: length 42.9
  BOTTOM w0.14: P2.2 17.34,7.18 17.07,7.44 17.07,8.35 14.74,10.68 14.74,18.69 14.8,18.75 U1.1 U1.8 14.8,21.29 14.74,21.36 14.74,42.08 14.29,42.53 14.29,44.6 15.2,45.52 P1.2
D1M_P2: length 44.5
  BOTTOM w0.14: P4.2 52.44,7.53 51.73,7.53 51.35,7.91 51.35,8.53 51.9,9.08 52.51,9.08 53.4,9.97 53.4,11.41 51.52,13.3 51.52,18.69 51.58,18.75 U4.1 U4.8 51.58,21.29 51.52,21.36 51.52,44.11 52.38,44.98 P3.2
D1M_P3: length 43.1
  BOTTOM w0.14: P5.2 94.85,6.66 93.99,7.52 93.99,9.79 92.59,11.19 92.59,18.69 92.66,18.75 U7.1 U7.8 92.66,21.29 92.59,21.36 92.59,44.29 93.46,45.16 P6.2
D1P_P1: length 42.9
  BOTTOM w0.14: P1.3 13.2,45.42 14.02,44.6 14.02,42.42 14.47,41.97 14.47,21.36 14.41,21.29 U1.7 U1.2 14.41,18.75 14.47,18.69 14.47,10.57 16.8,8.24 16.8,7.43 16.54,7.16 P2.3
D1P_P2: length 44.9
  BOTTOM w0.14: P3.3 50.38,44.94 51.25,44.08 51.25,21.36 51.18,21.29 U4.7 U4.2 51.18,18.75 51.25,18.69 51.25,13.19 53.14,11.3 53.14,10.08 52.4,9.35 51.79,9.35 51.08,8.64 51.08,7.8 51.62,7.26 52.44,7.26 P4.3
D1P_P3: length 43.1
  BOTTOM w0.14: P5.3 92.85,6.65 93.73,7.52 93.73,9.68 92.32,11.08 92.32,18.69 92.26,18.75 U7.2 U7.7 92.26,21.29 92.32,21.36 92.32,44.25 91.46,45.12 P6.3
DCP_CDP_TOGGLE_P1: length 4
  TOP w0.241: R12.1 3.11,31.49 3.05,31.54 R3.2 3.59,32.65 3.65,32.59 U2.4
DCP_CDP_TOGGLE_P2: length 3.9
  TOP w0.241: R26.1 39.89,31.98 39.8,32.07 R17.1 40.32,32.57 40.35,32.6 U5.4
DCP_CDP_TOGGLE_P3: length 3.9
  TOP w0.241: U8.4 82.13,32.6 82.08,32.54 R33.1 80.87,32.04 80.96,31.96 R42.1
ENA_HS_P1: length 2.4
  TOP w0.241: J1.8 28.91,11.09 28.94,11.05 R5.1
ENA_HS_P2: length 2.4
  TOP w0.241: R20.1 67.72,11.02 67.77,11.06 67.77,12.32
ENA_HS_P3: length 2.3
  TOP w0.241: R34.1 106.36,10.93 106.35,10.93 J5.8
RSTN_P1: length 13.8
  TOP w0.241: v1(9.89,19.4) C5.1 9,18.59 8.99,18.59 SW1.3 SW1.4
  BOTTOM w0.241: v1(9.89,19.4) 10.72,19.4 11.54,20.22 U1.5
RSTN_P2: length 13.7
  TOP w0.241: SW2.4 SW2.3 45.04,19.38 45.08,19.42 C16.1 46.6,19.42 v1(47.4,20.22)
  BOTTOM w0.241: U4.5 v1(47.4,20.22)
RSTN_P3: length 15.7
  TOP w0.241: v1(87.55,20.22) 86.67,20.22 85.34,18.89 C27.1 84.34,18.89 84.33,18.9 SW3.3 SW3.4
  BOTTOM w0.241: U7.5 v1(87.55,20.22)
RX_SEN/ENA_HS_P1: length 18.7
  BOTTOM w0.241: U1.9 15.46,20.62 16.89,22.05 24.53,22.05 27.64,18.95 27.64,16.15 J1.5
RX_SEN/ENA_HS_P2: length 20.2
  TOP w0.241: J3.5 66.5,16.13 66.5,18.69 65.05,20.14 55.09,20.14 v1(53.8,21.44)
  BOTTOM w0.241: U4.9 52.28,20.62 53.1,21.44 v1(53.8,21.44)
RX_SEN/ENA_HS_P3: length 17.7
  TOP w0.241: J5.5 105.09,15.99 105.09,18.78 104.7,19.18 96.75,19.18 v1(94.73,21.2)
  BOTTOM w0.241: U7.9 93.36,20.62 93.93,21.2 v1(94.73,21.2)
SCL/CD_P1: length 26.7
  TOP w0.241: JMP1.5 19.94,29.41 14.27,23.75 14.27,19.15 13.49,18.36 12.65,18.36 12.19,18.82 v1(12.19,19.64)
  BOTTOM w0.241: v1(12.19,19.64) 12.7,19.64 12.88,19.82 U1.4
SCL/CD_P2: length 27.1
  TOP w0.241: v1(49.18,19.35) 49.18,18.63 49.53,18.29 50.47,18.29 52.12,19.94 52.12,22.2 59.33,29.41 JMP9.5
  BOTTOM w0.241: U4.4 49.66,19.82 v1(49.18,19.35)
SCL/CD_P3: length 26.4
  TOP w0.241: v1(90.27,19.43) 90.27,18.87 90.86,18.29 92.05,18.29 92.9,19.14 92.9,24.96 97.36,29.41 JMP8.5
  BOTTOM w0.241: U7.4 90.66,19.82 v1(90.27,19.43)
SDA_P1: length 24.6
  TOP w0.241: v1(13.08,19.13) 13.08,23.6 21.44,31.95 JMP1.3
  BOTTOM w0.241: v1(13.08,19.13) 13.42,19.13 13.7,19.42 U1.3
SDA_P2: length 25.2
  TOP w0.241: v1(49.86,19.13) 51.31,20.58 51.31,22.35 60.91,31.95 JMP9.3
  BOTTOM w0.241: v1(49.86,19.13) 50.19,19.13 50.48,19.42 U4.3
SDA_P3: length 24.3
  TOP w0.241: JMP8.3 98.98,31.95 92.13,25.1 92.13,20.33 v1(90.93,19.13)
  BOTTOM w0.241: v1(90.93,19.13) 91.27,19.13 91.56,19.42 U7.3
SS_RXN_P2: length 39.4
  BOTTOM w0.14: P3.5 47.38,44.72 48.23,43.87 48.23,42.52 45.8,40.08 45.8,17.27 51.05,12.02 51.05,11.13 P4.5
SS_RXN_P3: length 43.8
  BOTTOM w0.14: P6.5 88.46,45.15 89.33,44.27 89.33,42.77 86.56,40.01 86.56,16.46 90.72,12.3 90.72,7.29 P5.5
SS_RXP_P2: length 39.5
  BOTTOM w0.14: P3.6 49.38,44.75 48.5,43.87 48.5,42.41 46.06,39.97 46.06,17.38 51.32,12.13 51.32,11.13 P4.6
SS_RXP_P3: length 43.8
  BOTTOM w0.14: P6.6 90.46,45.13 89.6,44.27 89.6,42.66 86.83,39.89 86.83,16.57 90.99,12.41 90.99,7.29 P5.6
SS_TXN_P2: length 37.7
  BOTTOM w0.14: P4.8 57.8,11.13 57.8,22.23 54.25,25.78 54.25,44.04 53.38,44.91 P3.8
SS_TXN_P3: length 43.6
  BOTTOM w0.14: P6.8 94.46,44.89 95.33,44.02 95.33,27.08 99.24,23.16 99.24,17.42 96.72,14.91 96.72,7.29 P5.8
SS_TXP_P2: length 37.7
  BOTTOM w0.14: P3.9 55.38,44.91 54.52,44.04 54.52,25.89 58.07,22.34 58.07,11.13 P4.9
SS_TXP_P3: length 43.6
  BOTTOM w0.14: P5.9 96.99,7.29 96.99,14.8 99.5,17.31 99.5,23.28 95.59,27.19 95.59,44.02 96.46,44.88 P6.9
SW_VCC_P1: length 18.4
  TOP w0.241: R47.1 R46.1 34.56,32.98 33.05,34.49 JMP1.2 31.37,35.75 34.7,39.08 34.7,41.05 34.25,41.49 U10.5 33.46,42.5 33.43,42.53 C35.1
SW_VCC_P2: length 19.1
  TOP w0.241: R49.1 73.6,31.4 73.63,31.43 R48.1 73.63,33.48 72.62,34.49 JMP9.2 70.36,35.86 73.46,38.96 73.46,41.1 73.09,41.46 U11.5 72.01,42.01 71.98,42.04 C37.1
SW_VCC_P3: length 20.5
  TOP w0.241: C39.1 111.68,42.76 111.71,42.73 U12.5 112.51,41.59 113.11,41 113.11,38.79 112.24,37.92 110.54,37.92 108.79,36.17 JMP8.2 111.05,34.49 112.08,33.46 R50.1 112.08,31.43 112.06,31.4 R51.1
N16790170: length 3
  TOP w0.241: R27.1 48.25,28.79 48.2,28.84 R28.2 46.91,28.84 46.9,28.85 U6.1
N16790175: length 7.7
  TOP w0.241: C22.1 44.97,27.46 44.53,27.9 44.53,29.29 45.03,29.8 U6.2 46.67,29.8 46.73,29.74 R28.1
N16793543: length 2.5
  TOP w0.241: U6.4 42.38,30.75 42.19,30.94 R26.2
N16795852: length 3
  TOP w0.241: R43.1 89.33,28.79 89.27,28.84 R44.2 87.98,28.84 87.97,28.85 U9.1
N16795856: length 7.7
  TOP w0.241: R44.1 87.8,29.74 87.74,29.8 U9.2 86.11,29.8 85.6,29.29 85.6,27.9 86.04,27.46 C33.1
N16796357: length 2.5
  TOP w0.241: R42.2 83.26,30.94 83.46,30.75 U9.4
N16796414: length 1.7
  TOP w0.241: D6.2 98.48,27.52 98.5,27.53 R35.2
N16797569: length 3
  TOP w0.241: U3.1 10.12,28.85 10.13,28.84 R14.2 11.42,28.84 11.47,28.78 R13.1
N16798025: length 5.4
  BOTTOM w0.241: C3.1 19.86,19.44 C4.1 17.78,19.44 17.24,18.9 L1.2 16.42,18.9 15.9,19.42 U1.12
N16798074: length 2.5
  TOP w0.241: U3.4 5.61,30.75 5.41,30.94 R12.2
N16798131: length 2.4
  TOP w0.241: D1.2 21.61,26.88 21.63,26.9 R4.2
N16810380: length 3.7
  BOTTOM w0.241: J1.4 25.11,14.88 25.1,14.89 R9.2 R11.1
N16810407: length 2.2
  BOTTOM w0.241: R7.1 6.38,8.44 6.35,8.47 J2.8
N16810514: length 2.4
  BOTTOM w0.241: R6.1 6.14,16.28 6.35,16.07 J2.2
N16813878: length 5.4
  BOTTOM w0.241: U4.12 52.68,19.42 53.2,18.9 L2.2 54.02,18.9 54.56,19.44 C15.1 56.64,19.44 C14.1
N16814597: length 5.4
  BOTTOM w0.241: U7.12 93.75,19.42 94.27,18.9 L3.2 95.09,18.9 95.63,19.44 C26.1 97.71,19.44 C25.1
N16860679: length 3.8
  BOTTOM w0.241: R30.1 R25.2 63.96,14.87 63.97,14.86 J3.4
N16860703: length 2.3
  BOTTOM w0.241: J4.8 42.6,8.65 42.65,8.59 R22.1
N16860789: length 2.3
  BOTTOM w0.241: J4.2 42.6,16.24 42.56,16.28 R21.1
N16861643: length 3.6
  BOTTOM w0.241: J5.4 102.55,14.73 102.54,14.74 R39.2 R41.1
N16861663: length 2.2
  BOTTOM w0.241: R38.1 77.83,12.46 77.84,12.47 J6.4
N16861667: length 2.2
  BOTTOM w0.241: J6.8 81.64,8.67 81.64,8.67 R37.1
N16861753: length 2.2
  BOTTOM w0.241: J6.2 81.64,16.27 81.63,16.28 R36.1
N16876268: length 7.7
  TOP w0.241: R14.1 9.95,29.74 9.89,29.8 U3.2 8.26,29.8 7.75,29.29 7.75,27.9 8.19,27.46 C11.1
N16883773: length 3.4
  TOP w0.241: R19.2 61.76,26.87 61.75,26.88 D4.2
N16915178: length 2.3
  TOP w0.241: R46.2 JMP1.4
N16915181: length 2.3
  TOP w0.241: R47.2 JMP1.6
N16916526: length 2.3
  TOP w0.241: R49.2 JMP9.6
N16916965: length 2.4
  TOP w0.241: R48.2 JMP9.4
N16917043: length 2.4
  TOP w0.241: R51.2 JMP8.6
N16917272: length 2.4
  TOP w0.241: R50.2 JMP8.4
N16929690: length 2.1
  BOTTOM w0.241: J1.2 28.91,18.68 28.94,18.71 R2.2
N16931613: length 2.2
  BOTTOM w0.241: R8.1 2.55,12.26 2.55,12.27 J2.4
N16933252: length 2.2
  BOTTOM w0.241: J3.2 67.77,18.66 67.8,18.69 R18.1
N16935144: length 2.2
  BOTTOM w0.241: J4.4 38.8,12.45 38.75,12.49 R24.1
N16936334: length 2.2
  BOTTOM w0.241: R32.2 106.38,18.56 106.35,18.53 J5.2
N168104220: length 4.8
  TOP w0.241: R5.2 33.28,9.93 33.62,10.27 D2.2
N168607180: length 4.7
  TOP w0.241: R20.2 D3.2
N168616820: length 5.2
  TOP w0.241: D5.2 111.01,11.26 109.68,9.93 R34.2

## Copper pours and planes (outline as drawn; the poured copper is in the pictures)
GND on TOP: 20.14,10.74 20.14,9.83 19.25,8.94 19.25,6.45 21.06,4.65 23.8,4.65 23.9,4.75 23.9,9.25 22.4,10.74
GND on BOTTOM: 20.22,10.69 20.22,0.66 23.9,0.66 23.9,10.69
GND on BOTTOM: 9.25,8.51 14.07,8.51 15.19,7.39 15.19,5.18 15.16,5.16 13.03,5.16 12.7,4.83 12.7,0.64 9.25,0.64
GND on L3_GND: 36.91,51.38 74.63,51.38 74.63,0.64 36.91,0.64
GND on L3_GND: 75.9,51.38 114.1,51.38 114.1,0.64 89.53,0.64 89.53,0.58 89.51,0.58 89.51,0.64 75.9,0.64
GND on L3_GND: 0.64,51.41 35.64,51.41 35.64,0.64 0.64,0.64
VBUS_DS_P1 on TOP: 15.35,38.31 9.78,38.31 9.78,33.48 9.91,33.36 17.02,33.36 17.02,33.4 20.29,36.68 20.29,47.52 19.15,48.67 16.81,48.67 16.81,46.86 19.13,46.86 19.46,46.53 19.46,42.42
VBUS_DS_P2 on TOP: 46.56,38.31 46.56,33.48 46.69,33.36 53.8,33.36 59.18,38.74 59.18,45.95 56.57,48.56 53.92,48.56 53.9,48.59 53.9,46.96 53.98,46.89 56.29,46.89 57.23,45.95 57.23,41.73 53.8,38.3
VBUS_DS_P3 on TOP: 87.63,38.3 87.63,33.48 87.76,33.36 91.41,33.36 91.41,38.3
VBUS_DS_P3 on TOP: 96.67,5.54 98.58,5.54 99.97,6.93 105.13,6.93 105.13,2.79 105.05,2.72 105.05,1.78 103.3,1.78 103.3,4.85 103,5.16 99.42,5.16 98.55,4.29 96.67,4.29
VBUS_DS_P3 on L2_PWR: 105.08,1.04 105.08,8.08 102.06,11.1 83.69,11.1 78.77,16.03 78.77,37.03 78.84,37.11 85.45,37.11 88.27,34.29 91.97,34.29 93.5,35.81 93.5,50.95 76.23,50.95 76.2,50.93 76.2,1.17 76.4,0.97 105,0.97
VBUS_US_P3 on TOP: 90.53,31.39 93.5,31.39 95.02,32.92 95.02,45.06 95.94,45.06 95.94,32.03 94.79,30.89 90.53,30.89
VBUS_US_P3 on L2_PWR: 79.76,36.07 79.76,17.27 84.71,12.32 97.33,12.32 97.33,16.47 96.2,16.47 93.91,14.18 88.14,14.18 81.66,20.66 81.66,29.8 84.27,32.41 95.1,32.41 97.28,34.59 97.28,45.54 97.23,45.49 94.46,45.49 94.34,45.36 94.34,34.67 93.07,33.4 87.53,33.4 84.86,36.07
VCC_EXT_P1 on L2_PWR: 16.3,29.59 5.25,29.59 4.57,28.91 4.57,22.94 12.06,15.45 16.38,15.45 18.29,17.35 19.48,17.35 24.99,11.84 24.99,0.71 24.94,0.66 35.61,0.66 35.64,0.69 35.64,51.33 35.56,51.41 1.02,51.41 0.64,51.03 0.64,33.32 16.18,33.32 16.3,33.2
VCC_EXT_P2 on L2_PWR: 52.95,29.46 41.9,29.46 41.35,28.91 41.35,22.94 48.84,15.45 53.16,15.45 55.07,17.36 58.59,17.36 65.68,10.26 67.31,10.26 67.36,10.21 67.36,0.64 74.55,0.64 74.6,0.69 74.6,51.41 37.13,51.41 37.01,51.28 37.01,33.2 53.25,33.2 53.25,29.76
VCC_EXT_P3 on BOTTOM: 77.95,35.74 77.95,27.76 84.71,27.76 84.71,35.74
VCC_EXT_P3 on L2_PWR: 95.89,31.33 84.84,31.33 82.42,28.91 82.42,22.94 89.92,15.45 94.23,15.45 96.14,17.36 99,17.36 100.78,15.58 100.79,15.58 106.64,9.73 106.65,9.73 106.68,9.7 106.68,0.69 114.1,0.69 114.1,15.53 114.05,15.58 114.05,34.5 114.07,34.53 114.07,51.41 98.91,51.41 98.94,51.38 98.94,34.38
VCC_US_P1 on TOP: 18.34,6.83 18.34,8.08 17.35,9.07 17.35,13.39 17.5,13.54 19.33,13.54 19.56,13.31 19.56,9.83 19.35,9.63 19.35,8.2 18.82,7.67 18.82,6.83
VCC_US_P1 on BOTTOM: 17.88,5.18 17.88,9.4 17.32,9.96 17.32,13.36 17.45,13.49 19.3,13.49 19.51,13.28 19.51,9.96 18.39,8.84 18.39,5.18
VCC_US_P1 on L2_PWR: 0.69,32.36 0.69,0.64 24.26,0.64 24.26,11.35 19.15,16.47 18.8,16.47 16.51,14.18 10.29,14.18 3.81,20.66 3.81,29.8 4.97,30.96 14.55,30.96 14.55,32.36
VCC_US_P2 on TOP: 65.41,1.5 65.41,4.42 65.74,4.75 65.74,9.14 63.7,9.14 63.7,1.5
VCC_US_P2 on L2_PWR: 37.01,32.41 37.01,0.66 66.12,0.66 66.12,8.89 64.8,8.89 57.23,16.47 55.58,16.47 53.29,14.18 47.07,14.18 40.59,20.66 40.59,29.8 42.03,31.24 51.82,31.24 51.82,32.41

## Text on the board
BOTTOM: LAYER 4 - BOTTOM SIDE
Board Geometry/Soldermask Bottom: SOLDERMASK BOTTOM
Package Geometry/Pastemask Bottom: PASTEMASK BOTTOM
Ref Des/Silkscreen Bottom: FOR EVALUATION ONLY | NOT FCC APPROVED FOR RESALE | SILKSCREEN BOTTOM
TOP: LAYER 1 - TOP SIDE
Board Geometry/Soldermask Top: SOLDERMASK TOP
Package Geometry/Pastemask Top: PASTEMASK TOP
Ref Des/Silkscreen Top: NC | LVL 3=NC | LVL 0 | LVL 2 | GND | HIGH | SCL/CD | SDA | VCC | CDP | CD | MID = NC | ENA_HS | LOW | LVL 1 | * | BOOST | HSDC112A | RX_SEN | SILKSCREEN TOP
L2_PWR: LAYER 2 - PWR PLANE
L3_GND: LAYER 3 - GND PLANE
NCROUTE_PATH: V-SCORE
XSECTION_CHART: *  SURFACE - AIR 0 MIL | *  DIELECTRIC - SOLDERMASK-0.8MIL 0.8 MIL | L1 TOP CONDUCTOR - COPPER_1/2OZ_PLATED 1.4 MIL | *  DIELECTRIC - FILL_0.125 4.92 MIL | L2 L2_GND PLANE - COPPER_1.0OZ 1.4 MIL | *  DIELECTRIC - CORE_1.10 43.31 MIL | L3 L3_PWR PLANE - COPPER_1.0OZ 1.4 MIL | L4 BOTTOM CONDUCTOR - COPPER_1/2OZ_PLATED 1.4 MIL | DESIGN CROSS SECTION CHART | ___________________________ | TOTAL THICKNESS 60.35 MIL | 1-4
DIMENSION: FABRICATION DRAWING | CAD ORIGIN
User.6: LAYER 1 | LAYER 2 | LAYER 3 | LAYER 4 | LAYER | NO. | TABLE 1: | TOP | L2_GND | L3_PWR | BOTTOM | NAME | DIFFIRENTIAL PAIR | IMPEDANCE (OHMS) | 90  +/- 10% | DIFF TRACE | WIDTH | 0.0055" | SPACING | 0.005" | SINGLE ENDED | 45 +/- 10% | TRACE WIDTH | 0.0095" | REFERENCE | SPECIAL FAB NOTES: | PLACE DRILL CHART HERE: | 1:FAB SHOP MUST FOLLOW THE SOLDER MASK REVIEW LAYERS. | 2: | MIN. ANNULAR RING 2 MIL EXTERNAL PER IPC-6012C | REGISTRATION TOLERANCES: METAL +/- X MIL,HOLES +/- X MIL | IMPEDANCE CONTROL: | BOARD SIZE (REFER ALSO ARRAY/PANEL PROFILING INFORMATION) | MIXED DIELECTRIC: | LAMINATE MATERIAL: | THICKNESS: | TOLERANCE: | COPPER THICKNESS (FINISHED): | BOARD FINISH: | NUMBER OF LAYERS: | MIN. TRACK WIDTH: | MIN. CLEARANCE  : | MIN. VIA PAD/DRILL: | THIEVING ALLOWED: | X | OUTER: | INNER SIGNAL: | INNER PLANE: | OTHER: | SILKSCREEN: | SOLDERMASK: (PER IPC-6011,6012) | BOARD SURFACE TREATMENT: | ADDITIONAL REQUIREMENTS: | VENDOR MARKING: | SILKSCREEN COLOR: | SOLDERMASK COLOR: | THROUGH-HOLE VIA TREATMENT: | VIA FILL USING NON-CONDUCTIVE EPOXY: | FOR WIRE BONDING: | VENDOR DATE CODE,UL,LOGO: | IPC-6012C CLASS 3 | FR-4 HIGH Tg | 0.062" +/-10% | IPC-6012C CLASS 2 | MICRO-SECTION | CERTIFICATES OF COMPLIANCE | NICKEL/GOLD (ENIG) | IMMERSION TIN | HARD GOLD | IN AN OPEN AREA | 1/4 OZ. | OPEN | NO | 4 | 5.5 MIL | 5.0 MIL | 20/10 MIL | NONE | DESIGN INFORMATION | ROGERS 4350B | 0.093" +/-10% | YES | TDR REPORTS/COUPONS | WHITE | GREEN | SOFT GOLD | TENTED | 1/2 OZ. | BOW & TWIST: | ORGANIC (OSP) | OTHER | WHERE INDICATED (SEE DRAWING) | YES - SEE TABLE 1 | ETCH | IDENTIFIER: | BLUE | RoHS | 1.0 OZ. | SILKSCREEN | PER SUPPLIED ARTWORK | ALL x MIL VIAS | ELECTRICAL TEST | UL 94V-0 | HASL | 2.0 OZ. | BREAK-AWAY | ENEPIG
User.7: ASSEMBLY TOP
User.8: ASSEMBLY BOTTOM
User.10: FIGURE | FINISHED_SIZE | 10.0 | 27.56 | 36.22 | 40.16 | 90.55 | 47.24 | 114.17x35.43 | DRILL CHART: TOP to BOTTOM | ALL UNITS ARE IN MILS | TOLERANCE_DRILL | +3.0/-3.0 | +3.15/-3.15 | +1.97/-1.97 | PLATED | NON-PLATED | QTY | 181 | 32 | 4 | 102 | 8 | 2 | 331 | TOTAL HOLES:
